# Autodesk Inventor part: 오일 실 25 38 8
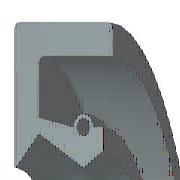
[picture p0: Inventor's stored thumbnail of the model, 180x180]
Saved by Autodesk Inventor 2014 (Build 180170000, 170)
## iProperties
Created: 2012-02
Part Number: 오일 실 25 38 8
Material: 고무
Description: 오일-실
Document SubType Name: Modeling
Standard: KS B 2804
Designer: mduedu
Standards Organization: KS
Language: ko-KR
Size Designation: D - 25 38 8
Categories: <MemberInstance><Categories><Category DisplayName="샤프트 부품" InternalName="7f7aeb1f-a693-4053-b835-cee3144e0d98" Mnemonic="SHFT"><Category DisplayName="실링" Intern
Density: 0.93 g/cm^3
Appearance: 고무 - 검은색 - 버전 1.1
IsCustomPart: 1
Author: mduedu
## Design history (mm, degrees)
revolve "본체" stored, may be unused: angle "d17" = 90 deg
revolve "스프링1" stored, may be unused: angle "d18" = 90 deg
body "Solid1"
sketch "스케치1"
  geometry: L1 (0, 19)-(8, 19); L2 (8, 17.25)-(1.75, 17.25); L3 (1.75, 14.25)-(4.9, 12.5); L4 (4.9, 12.5)-(0, 12.5); L5 (0, 0)-(9.586, 0) reference; L6 (4.9, 12.5)-(6.3, 13.375); L7 (0, 18)-(0, -3) reference; L8 (-1.941, 0)-(11.507, 0) reference; L9 (4.2, 14.6)-(1.75, 15.21); L10 (1.75, 15.21)-(1.75, 17.25); L11 (0, 19)-(0, 12.588); L12 (4.9, 12.5)-(0, 12.5); L13 (1.75, 14.25)-(0.152, 12.528); L14 (8, 19)-(8, 17.25); L15 (5.6, 14.6)-(6.3, 14.6); L16 (6.3, 14.6)-(6.3, 13.375); C1 r 0.455 at (4.9, 14.6); A1 r 0.7 centre (4.9, 14.6) between (5.6, 14.6) and (4.2, 14.6); A2 r 0.088 centre (0.087, 12.588) between (0, 12.588) and (0.152, 12.528); 1 further point
  constraints: 28 end point, 5 horizontal alignment, 5 point on line, 4 point on circle, 4 vertical alignment, 3 centre point, 3 tangent, 2 collinear, 2 horizontal, 2 perpendicular, 1 coincident, 1 parallel
  dimensions: "d0" = 38 diameter of L1 L5 (= SD2); "d1" = 1.75 distance of L1.end L2.start (= SD); "d2" = 0.91 diameter of C1 (= SPDI); "d3" = 1.4 diameter of A1 (= SPDA); "d4" = 25 diameter of L3.end L5 (= NND); "d5" = 28.5 diameter of L3.start L5 (= TKDM); "d7" = 30.42 diameter of L9.end L5 (= TKDM + 0.24 x SWDT); "d8" = 1.75 distance between parallel lines of L11 L10 (= SD); "d9" = 4.9 distance from line of L11 C1.centre (= SPDST); "d10" = 29.2 diameter of C1.centre L5 (= HLDM); "d11" = 0.0875 radius of A2 (= 0.25 x LAB); "d12" = 6.3 distance between parallel lines of L11 L16 (= SDI); "d13" = 26.75 diameter of L6.end L5 (= ABDM); "d14" = 8 distance from line of L11 L1.end (= SWDT)
fillet "모깎기1" dims "d6" = 0.3 (= RR)
other parameters: "SD2" = 38 [user parameter; used in 1 equation term], "SWDT" = 8 [user parameter; used in 2 equation terms], "RR" = 0.3 [user parameter; used in 1 equation term], "SD" = 1.75 [user parameter; used in 2 equation terms], "NND" = 25 [user parameter; used in 1 equation term], "SPDA" = 1.4 [user parameter; used in 1 equation term], "SPDI" = 0.91 [user parameter; used in 1 equation term], "TKDM" = 28.5 [user parameter; used in 2 equation terms], "HLDM" = 29.2 [user parameter; used in 1 equation term], "ABDM" = 26.75 [user parameter; used in 1 equation term], "SDI" = 6.3 [user parameter; used in 1 equation term], "SPDST" = 4.9 [user parameter; used in 1 equation term], "LAB" = 0.35 [user parameter; used in 1 equation term], "d15" = 0, "d16" = 0, "d19" = 0
